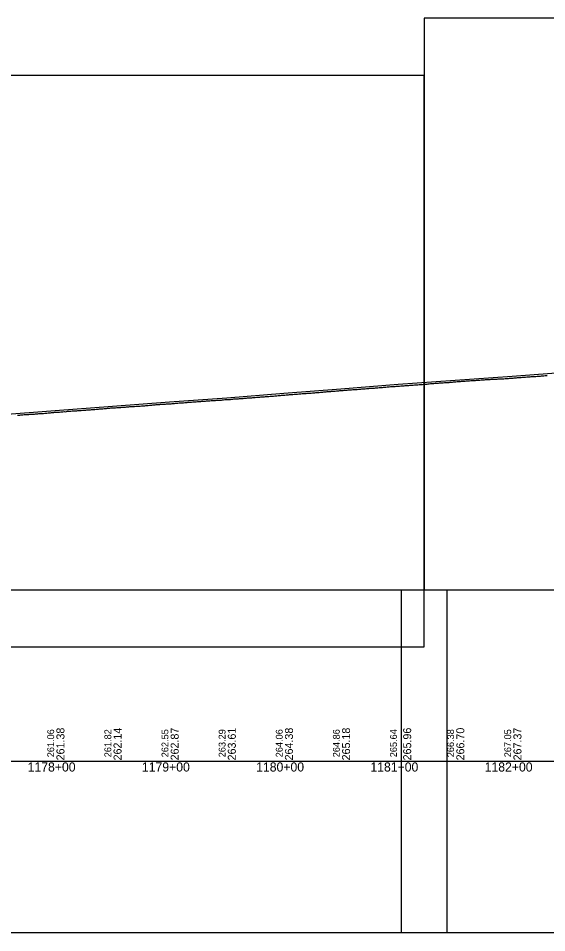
# Model space of a CAD drawing. Extents: x 2898 to 49495, y -15038 to -13538.
# Drawn here: x 7121 to 7583, y -15038 to -14238 of the extents above; entities that cross this region are included whole.
import ezdxf

# ---------------------------------------------------------------- set-up
doc = ezdxf.new("R2010")
doc.units = 0
for name, color, linetype in [('RD_DDB_Profile_EX', 7, 'Continuous'), ('RD_DDB_Profile_PR', 7, 'Continuous'), ('RD_DDB_StaTX', 7, 'Continuous'), ('RD_DDB_StripGrade', 7, 'Continuous'), ('RD_GPK_Profile_Cell', 7, 'Continuous'), ('RD_SHT_ShtClip', 7, 'Continuous')]:
    doc.layers.add(name, color=color, linetype=linetype)

msp = doc.modelspace()

# ---------------------------------------------------------------- linework, layer by layer
at = {"layer": 'RD_DDB_Profile_EX'}
for points in [[(7546.01, -14553.77), (7547.01, -14553.67), (7548.01, -14553.62), (7549.02, -14553.52), (7550.01, -14553.52), (7551.01, -14553.42), (7552.01, -14553.32), (7553.01, -14553.27), (7554, -14553.17), (7555.02, -14553.12), (7556.01, -14553.07), (7557.02, -14553.02), (7558, -14552.87), (7559.01, -14552.77), (7560.01, -14552.72), (7561.01, -14552.67), (7562, -14552.58), (7563.01, -14552.48), (7564.02, -14552.38), (7565, -14552.38), (7566.02, -14552.28), (7567.01, -14552.23), (7568, -14552.08), (7569, -14552.03), (7570.01, -14551.98), (7571.01, -14551.88), (7572.01, -14551.78), (7573, -14551.78), (7574.01, -14551.73), (7575, -14551.63), (7576, -14551.63), (7577.01, -14551.43), (7578.01, -14551.43), (7579, -14551.38), (7580.02, -14551.28), (7581.01, -14551.18), (7582, -14551.08), (7583, -14551.03), (7584, -14550.93)], [(7445.74, -14560.82), (7446.74, -14560.72), (7447.73, -14560.72), (7448.73, -14560.67), (7449.74, -14560.57), (7450.74, -14560.47), (7451.73, -14560.42), (7452.73, -14560.32), (7453.73, -14560.27), (7454.73, -14560.22), (7455.73, -14560.12), (7456.73, -14560.02), (7457.73, -14559.97), (7458.73, -14559.92), (7459.73, -14559.82), (7460.73, -14559.72), (7461.74, -14559.72), (7462.73, -14559.62), (7463.73, -14559.57), (7464.73, -14559.52), (7465.73, -14559.47), (7466.73, -14559.32), (7467.73, -14559.22), (7468.73, -14559.17), (7469.73, -14559.12), (7470.73, -14559.07), (7471.73, -14558.92), (7472.73, -14558.82), (7473.76, -14558.81), (7474.73, -14558.72), (7475.73, -14558.57), (7476.72, -14558.47), (7477.73, -14558.47), (7478.73, -14558.42), (7479.73, -14558.32), (7480.72, -14558.17), (7481.73, -14558.12), (7482.73, -14558.07), (7483.73, -14558.02), (7484.73, -14557.97), (7485.73, -14557.82), (7486.73, -14557.72), (7487.72, -14557.67), (7488.73, -14557.62), (7489.73, -14557.52), (7490.73, -14557.47), (7491.72, -14557.37), (7492.73, -14557.27), (7494.02, -14557.17), (7495.02, -14557.07), (7496.02, -14557.02), (7497.02, -14557.02), (7498.02, -14556.97), (7499.02, -14556.87), (7500.02, -14556.82), (7501.02, -14556.77), (7502.01, -14556.62), (7503.02, -14556.57), (7504.02, -14556.52), (7505.02, -14556.37), (7506.02, -14556.32), (7507.02, -14556.32), (7508.02, -14556.12), (7509.01, -14556.07), (7510.02, -14555.97), (7511.02, -14555.92), (7512.01, -14555.87), (7513.02, -14555.77), (7514.02, -14555.72), (7515.02, -14555.67), (7516.01, -14555.57), (7517.02, -14555.42), (7518.02, -14555.37), (7519.01, -14555.32), (7520.02, -14555.27), (7521.02, -14555.27), (7522.02, -14555.17), (7523.01, -14555.07), (7524.02, -14554.97), (7525.02, -14554.92), (7526.01, -14554.82), (7527.01, -14554.77), (7528.02, -14554.77), (7529.02, -14554.67), (7530.01, -14554.62), (7531.02, -14554.52), (7532.02, -14554.47), (7533.01, -14554.52), (7534.01, -14554.42), (7535.02, -14554.32), (7536.02, -14554.27), (7537.01, -14554.22), (7538.02, -14554.12), (7539.02, -14554.12), (7540.01, -14554.07), (7541.01, -14554.02), (7542.01, -14553.87), (7543.02, -14553.87), (7544.01, -14553.82), (7545.01, -14553.82), (7546.01, -14553.77)], [(7349.42, -14568.47), (7350.42, -14568.42), (7351.41, -14568.27), (7352.42, -14568.17), (7353.42, -14568.17), (7354.41, -14568.12), (7355.41, -14568.02), (7356.42, -14567.87), (7357.41, -14567.77), (7358.41, -14567.67), (7359.42, -14567.67), (7360.42, -14567.67), (7361.41, -14567.52), (7362.41, -14567.42), (7363.42, -14567.37), (7364.41, -14567.22), (7365.41, -14567.17), (7366.42, -14567.12), (7367.41, -14567.07), (7368.41, -14566.97), (7369.41, -14566.87), (7370.41, -14566.77), (7371.41, -14566.67), (7372.01, -14566.64), (7372.41, -14566.62), (7372.89, -14566.59), (7373.41, -14566.57), (7373.84, -14566.54), (7374.41, -14566.52), (7375.41, -14566.42), (7376.42, -14566.37), (7377.41, -14566.32), (7378.41, -14566.22), (7379.41, -14566.12), (7380.41, -14566.07), (7381.41, -14565.92), (7382.41, -14565.82), (7383.41, -14565.77), (7384.41, -14565.77), (7385.41, -14565.62), (7386.41, -14565.52), (7387.41, -14565.42), (7388.41, -14565.32), (7389.41, -14565.37), (7390.41, -14565.27), (7391.41, -14565.12), (7392.41, -14565.02), (7393.41, -14564.97), (7394.41, -14564.87), (7395.42, -14564.82), (7396.41, -14564.67), (7397.41, -14564.57), (7398.41, -14564.57), (7399.41, -14564.47), (7400.41, -14564.37), (7401.41, -14564.33), (7402.41, -14564.22), (7403.41, -14564.17), (7404.41, -14564.13), (7405.4, -14563.98), (7406.41, -14563.88), (7407.41, -14563.78), (7408.4, -14563.73), (7408.74, -14563.73), (7409.74, -14563.63), (7410.74, -14563.58), (7411.74, -14563.53), (7412.74, -14563.48), (7413.74, -14563.33), (7414.74, -14563.27), (7415.74, -14563.23), (7416.74, -14563.18), (7417.74, -14563.12), (7418.74, -14563.07), (7419.74, -14562.92), (7420.74, -14562.82), (7421.73, -14562.72), (7422.74, -14562.67), (7423.74, -14562.57), (7424.74, -14562.52), (7425.73, -14562.42), (7426.74, -14562.32), (7427.74, -14562.22), (7428.74, -14562.17), (7429.73, -14562.17), (7430.74, -14562.12), (7431.74, -14562.02), (7432.73, -14561.92), (7433.73, -14561.87), (7434.74, -14561.77), (7435.74, -14561.72), (7436.73, -14561.62), (7437.73, -14561.47), (7438.74, -14561.37), (7439.74, -14561.37), (7440.73, -14561.32), (7441.74, -14561.22), (7442.74, -14561.07), (7443.73, -14561.02), (7444.73, -14560.92), (7445.74, -14560.82)], [(7150.12, -14583.43), (7151.11, -14583.38), (7152.11, -14583.28), (7153.11, -14583.18), (7154.12, -14583.13), (7155.11, -14583.03), (7156.11, -14582.98), (7157.12, -14582.93), (7158.11, -14582.88), (7159.11, -14582.83), (7160.11, -14582.68), (7161.12, -14582.53), (7162.11, -14582.63), (7163.11, -14582.38), (7164.12, -14582.23), (7165.11, -14582.23), (7166.11, -14582.18), (7167.11, -14582.08), (7168.11, -14581.98), (7169.11, -14581.93), (7170.11, -14581.93), (7171.12, -14581.88), (7172.11, -14581.78), (7173.11, -14581.73), (7174.11, -14581.63), (7175.11, -14581.58), (7176.11, -14581.53), (7177.11, -14581.43), (7178.11, -14581.38), (7179.11, -14581.28), (7180.11, -14581.18), (7181.11, -14581.13), (7182.11, -14581.08), (7183.11, -14580.98), (7184.11, -14580.98), (7185.11, -14580.83), (7186.11, -14580.68), (7187.11, -14580.63), (7188.11, -14580.58), (7189.11, -14580.48), (7190.11, -14580.43), (7191.11, -14580.38), (7192.1, -14580.28), (7193.11, -14580.23), (7194.11, -14580.08), (7195.1, -14580.03), (7196.11, -14579.93), (7197.11, -14579.83), (7198.11, -14579.78), (7199.1, -14579.68), (7200.11, -14579.58), (7201.11, -14579.48), (7202.1, -14579.38), (7203.11, -14579.38), (7204.11, -14579.33), (7205.11, -14579.23), (7206.1, -14579.18), (7207.11, -14579.08), (7208.11, -14578.93), (7209.1, -14578.88), (7210.11, -14578.83), (7210.76, -14578.83), (7211.75, -14578.73), (7212.76, -14578.68), (7213.76, -14578.68), (7214.75, -14578.68), (7215.76, -14578.53), (7216.76, -14578.43), (7217.76, -14578.33), (7218.75, -14578.23), (7219.75, -14578.13), (7220.75, -14578.08), (7221.74, -14578.03), (7222.75, -14578.08), (7223.75, -14577.93), (7224.75, -14577.83), (7225.75, -14577.78), (7226.75, -14577.68), (7227.75, -14577.68), (7228.74, -14577.53), (7229.75, -14577.48), (7230.75, -14577.43), (7231.74, -14577.38), (7232.75, -14577.28), (7233.75, -14577.13), (7234.75, -14577.08), (7235.74, -14577.03), (7236.75, -14576.93), (7237.75, -14576.83), (7238.74, -14576.73), (7239.74, -14576.63), (7240.75, -14576.58), (7241.75, -14576.48), (7242.74, -14576.43), (7243.75, -14576.33), (7244.75, -14576.28), (7245.74, -14576.18), (7246.74, -14576.13), (7247.75, -14576.03), (7248.74, -14575.98), (7249.74, -14575.93)], [(7249.74, -14575.93), (7250.75, -14575.88), (7251.75, -14575.83), (7252.74, -14575.73), (7253.74, -14575.68), (7254.75, -14575.68), (7255.74, -14575.48), (7256.74, -14575.38), (7257.74, -14575.33), (7258.74, -14575.28), (7259.74, -14575.28), (7260.74, -14575.18), (7261.75, -14575.03), (7262.74, -14574.98), (7263.74, -14574.88), (7264.74, -14574.83), (7265.74, -14574.88), (7266.74, -14574.68), (7267.74, -14574.68), (7268.75, -14574.58), (7269.74, -14574.43), (7270.74, -14574.33), (7271.74, -14574.23), (7272.74, -14574.18), (7273.74, -14574.08), (7274.74, -14574.03), (7275.74, -14573.98), (7276.74, -14573.88), (7277.74, -14573.83), (7278.74, -14573.83), (7279.74, -14573.68), (7280.74, -14573.63), (7281.74, -14573.53), (7282.73, -14573.48), (7283.74, -14573.43), (7284.74, -14573.33), (7285.73, -14573.23), (7286.74, -14573.13), (7287.74, -14573.08), (7288.74, -14573.03), (7289.73, -14572.93), (7290.74, -14572.88), (7291.74, -14572.88), (7292.73, -14572.83), (7293.74, -14572.73), (7294.74, -14572.68), (7295.74, -14572.58), (7296.73, -14572.48), (7297.74, -14572.48), (7298.74, -14572.43), (7299.73, -14572.28), (7300.73, -14572.23), (7301.74, -14572.08), (7302.73, -14572.08), (7303.73, -14571.98), (7304.74, -14571.93), (7305.74, -14571.88), (7306.73, -14571.83), (7307.74, -14571.73), (7308.74, -14571.63), (7309.73, -14571.53), (7310.73, -14571.53), (7311.74, -14571.38), (7312.73, -14571.28), (7313.73, -14571.28), (7314.73, -14571.23), (7315.74, -14571.13), (7316.73, -14571.03), (7317.73, -14570.98), (7318.74, -14570.88), (7319.73, -14570.73), (7320.73, -14570.68), (7321.73, -14570.63), (7322.74, -14570.53), (7323.42, -14570.53), (7324.43, -14570.43), (7325.43, -14570.38), (7326.42, -14570.33), (7327.42, -14570.23), (7328.43, -14570.18), (7329.42, -14570.03), (7330.42, -14569.93), (7331.43, -14569.88), (7332.42, -14569.83), (7333.42, -14569.78), (7334.42, -14569.67), (7335.42, -14569.63), (7336.42, -14569.53), (7337.42, -14569.38), (7338.42, -14569.32), (7339.42, -14569.32), (7340.42, -14569.27), (7341.42, -14569.12), (7342.42, -14569.02), (7343.42, -14568.97), (7344.42, -14568.92), (7345.42, -14568.82), (7346.42, -14568.72), (7347.42, -14568.67), (7348.41, -14568.47), (7349.42, -14568.47)], [(7120.34, -14585.78), (7121.33, -14585.68), (7122.33, -14585.54), (7123.34, -14585.39), (7124.34, -14585.34), (7125.12, -14585.28), (7126.12, -14585.23), (7127.12, -14585.18), (7128.11, -14585.14), (7129.12, -14585.13), (7130.12, -14585.03), (7131.11, -14584.88), (7132.12, -14584.88), (7133.12, -14584.73), (7134.12, -14584.68), (7135.11, -14584.68), (7136.12, -14584.58), (7137.12, -14584.48), (7138.11, -14584.43), (7139.12, -14584.33), (7140.12, -14584.28), (7141.11, -14584.13), (7142.11, -14584.13), (7143.12, -14584.08), (7144.12, -14583.98), (7145.11, -14583.88), (7146.12, -14583.88), (7147.12, -14583.78), (7148.11, -14583.58), (7149.11, -14583.53), (7150.12, -14583.43)]]:
    msp.add_lwpolyline(points, dxfattribs=at)
at = {"layer": 'RD_DDB_Profile_PR'}
msp.add_lwpolyline([(6653.38, -14599.42), (6703.38, -14600.43), (6753.38, -14600.58), (6803.38, -14599.77), (6853.38, -14598.61), (6903.38, -14597.21), (6953.38, -14594.77), (7003.38, -14591.95), (7053.38, -14588.85), (7103.38, -14585.53), (7153.38, -14581.57), (7203.38, -14577.76), (7253.38, -14574.1), (7303.38, -14570.42), (7353.38, -14566.57), (7403.38, -14562.58), (7453.38, -14558.69), (7503.38, -14554.95), (7553.38, -14551.64), (7603.38, -14547.74)], dxfattribs=at)
at = {"layer": 'RD_GPK_Profile_Cell'}
msp.add_line((2976.05, -14888.47), (48721.13, -14888.47), dxfattribs=at)
at = {"layer": 'RD_SHT_ShtClip'}
for points in [[(8976.22, -14738.47), (8976.22, -14238.47), (8976.22, -14238.47), (7476.38, -14238.47), (7476.38, -14738.47)], [(7476.22, -14788.47), (7476.22, -14288.47), (7476.22, -14288.47), (5976.38, -14288.47), (5976.38, -14788.47)], [(5956.38, -14738.47), (7496.05, -14738.47), (7496.05, -15038.47), (5956.38, -15038.47)], [(7456.38, -14738.47), (8996.05, -14738.47), (8996.05, -15038.47), (7456.38, -15038.47)]]:
    msp.add_lwpolyline(points, close=True, dxfattribs=at)

# ---------------------------------------------------------------- texts
at = {"layer": 'RD_DDB_StaTX'}
for s, p in [('1178+00', (7129.18, -14897.47)), ('1179+00', (7229.18, -14897.47)), ('1180+00', (7329.18, -14897.47)), ('1181+00', (7429.18, -14897.47)), ('1182+00', (7529.18, -14897.47))]:
    msp.add_text(s, height=8, dxfattribs=at).set_placement(p)
at = {"layer": 'RD_DDB_StripGrade'}
for s, height, p in [('261.06', 6, (7152.38, -14884.98)), ('261.38', 7, (7161.38, -14887.72)), ('261.82', 6, (7202.38, -14884.98)), ('262.14', 7, (7211.38, -14887.72)), ('262.55', 6, (7252.38, -14884.98)), ('262.87', 7, (7261.38, -14887.72)), ('263.29', 6, (7302.38, -14884.98)), ('263.61', 7, (7311.38, -14887.72)), ('264.06', 6, (7352.38, -14884.98)), ('264.38', 7, (7361.38, -14887.72)), ('264.86', 6, (7402.38, -14884.98)), ('265.18', 7, (7411.38, -14887.72)), ('265.64', 6, (7452.38, -14884.98)), ('265.96', 7, (7464.88, -14887.72)), ('266.38', 6, (7502.38, -14884.98)), ('266.70', 7, (7511.38, -14887.72)), ('267.05', 6, (7552.38, -14884.98)), ('267.37', 7, (7561.38, -14887.72))]:
    msp.add_text(s, height=height, rotation=90, dxfattribs=at).set_placement(p)

doc.saveas('drawing.dxf')
